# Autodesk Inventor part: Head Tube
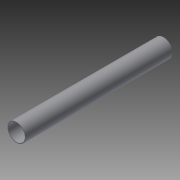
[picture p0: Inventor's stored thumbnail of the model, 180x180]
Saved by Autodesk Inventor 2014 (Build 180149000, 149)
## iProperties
Shininess: 64.0
Length Units: 11272
Angle Units: 11279
Time Units: 11290
Mass Units: 11286
Length Display Precision: 3
Angle Display Precision: 2
Compacted: True
Part Number: Head Tube
Document SubType Name: Modeling
Created: 2002-09
Designer: Autodesk, Inc.
Mass: 25.0785 g
Surface Area: 397.116 cm^2
Volume: 25.0785 cm^3
Density: 1 g/cm^3
Material: Generic
Appearance: Default
Density: 0.0
Volumn: 0.0
Area: 0.0
PropertySet Name: Model Information
Control State: 0
Master: False
Checked Out: False
Author: Autodesk, Inc.
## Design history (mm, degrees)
sketch "Sketch1"
  geometry: C1 r 14.287 at (0, 0); 1 further point
  constraints: 1 centre point, 1 coincident
  dimensions: "d0" = 28.575 diameter of C1 (= OD)
extrude "Extrusion1" new body sketch "Sketch1" distance "d1" = 230.2002; taper "d2" = 0 deg
shell "Shell1" dims "d3" = 1.27
body "Solid1"
other parameters: "OD" = 28.575 [user parameter; used in 1 equation term]
